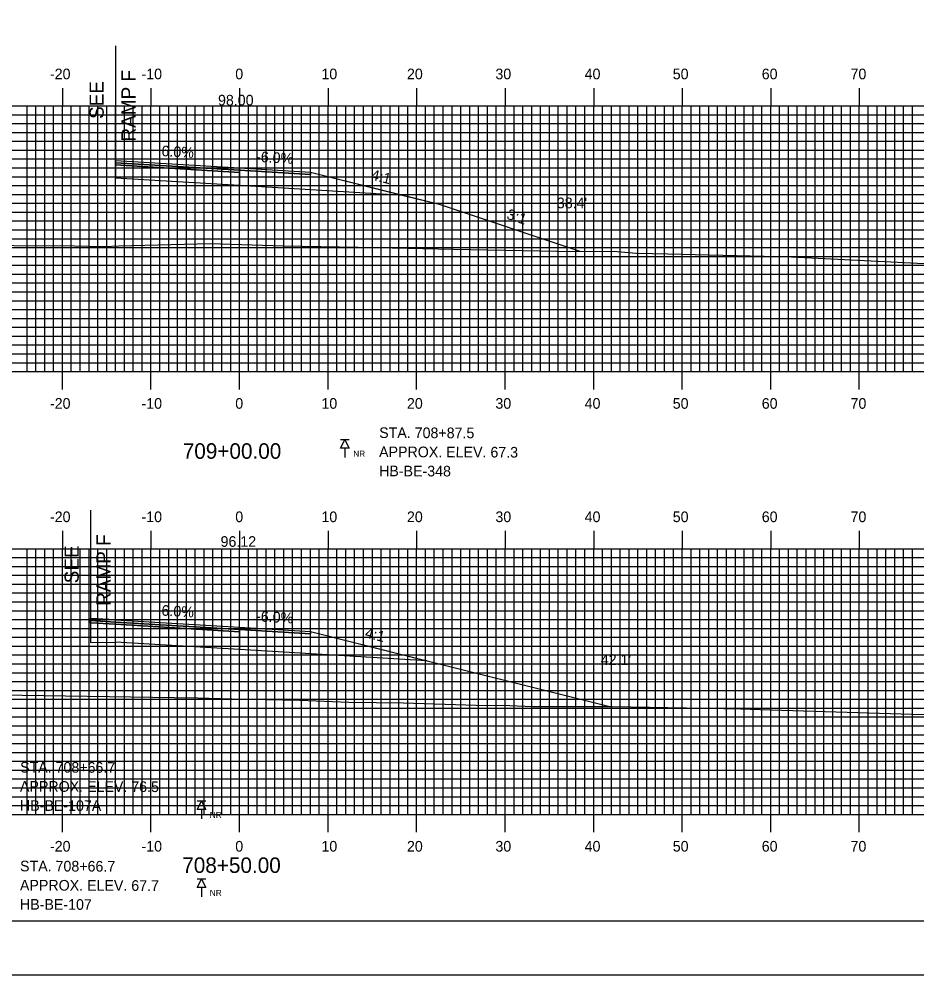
# Model space of a CAD drawing. Extents: x 854510 to 854853, y 364366 to 364586.
# Drawn here: x 854650.8 to 854752.2, y 364365.7 to 364473.6 of the extents above; entities that cross this region are included whole.
import ezdxf

# ---------------------------------------------------------------- set-up
doc = ezdxf.new("R2010")
doc.units = 0
for name, color, linetype in [('ANNOTATION', 7, 'Continuous'), ('BORDER', 7, 'Continuous'), ('BORING - NO REFUSAL', 7, 'Continuous'), ('D_Roadway_Centerline', 7, 'Continuous'), ('D_Roadway_Centerline_Text', 7, 'Continuous'), ('D_Roadway_Edge_Shoulder', 7, 'Continuous'), ('D_Roadway_Edge_TW', 7, 'Continuous'), ('D_Roadway_Pavement', 7, 'Continuous'), ('D_Roadway_SlopeLines', 7, 'Continuous'), ('D_Roadway_SubGrade', 7, 'Continuous'), ('D_Text_Standard', 7, 'Continuous'), ('H_V ANNOTATION', 7, 'Continuous'), ('MAJOR', 7, 'Continuous'), ('MINOR', 7, 'Continuous'), ('PLOT BOUNDARY', 7, 'Continuous'), ('S_Roadway_Centerline', 7, 'Continuous')]:
    doc.layers.add(name, color=color, linetype=linetype)

msp = doc.modelspace()

# ---------------------------------------------------------------- linework, layer by layer
at = {"layer": 'BORDER'}
msp.add_lwpolyline([(854526.14, 364371.79), (854846.14, 364371.79), (854846.14, 364581.79), (854526.14, 364581.79)], close=True, dxfattribs=at)
at = {"layer": 'BORING - NO REFUSAL'}
for p, q in [((854688.12, 364426.09), (854687.16, 364426.09)), ((854687.64, 364425.13), (854687.64, 364424.07)), ((854671.92, 364385.29), (854670.96, 364385.29)), ((854671.44, 364384.33), (854671.44, 364383.27)), ((854671.92, 364376.49), (854670.96, 364376.49)), ((854671.44, 364375.53), (854671.44, 364374.47))]:
    msp.add_line(p, q, dxfattribs=at)
for points in [[(854687.64, 364426.09), (854688.12, 364425.13), (854687.16, 364425.13)], [(854671.44, 364385.29), (854671.92, 364384.33), (854670.96, 364384.33)], [(854671.44, 364376.49), (854671.92, 364375.53), (854670.96, 364375.53)]]:
    msp.add_lwpolyline(points, close=True, dxfattribs=at)
at = {"layer": 'D_Roadway_Centerline'}
msp.add_lwpolyline([(854661.74, 364457.62), (854675.74, 364456.78), (854683.74, 364456.3), (854694.27, 364453.67), (854698.27, 364452.67), (854714.17, 364447.37)], dxfattribs=at)
at = {"layer": 'D_Roadway_Edge_Shoulder'}
for points in [[(854675.74, 364456.78), (854683.74, 364456.3), (854683.74, 364456.05), (854675.74, 364456.53)], [(854661.74, 364405.75), (854658.92, 364405.92), (854658.92, 364405.67), (854661.74, 364405.5)], [(854675.74, 364404.91), (854683.74, 364404.43), (854683.74, 364404.18), (854675.74, 364404.66)]]:
    msp.add_lwpolyline(points, close=True, dxfattribs=at)
at = {"layer": 'D_Roadway_Edge_TW'}
for points in [[(854661.74, 364457.62), (854675.74, 364456.78), (854675.74, 364456.53), (854661.74, 364457.37)], [(854661.74, 364405.75), (854675.74, 364404.91), (854675.74, 364404.66), (854661.74, 364405.5)]]:
    msp.add_lwpolyline(points, close=True, dxfattribs=at)
at = {"layer": 'D_Roadway_Pavement'}
for points in [[(854661.74, 364457.37), (854675.74, 364456.53), (854675.74, 364456.28), (854661.74, 364457.12)], [(854661.74, 364405.5), (854658.92, 364405.67), (854658.92, 364405.42), (854661.74, 364405.25)], [(854661.74, 364405.5), (854675.74, 364404.66), (854675.74, 364404.41), (854661.74, 364405.25)]]:
    msp.add_lwpolyline(points, close=True, dxfattribs=at)
for points in [[(854675.74, 364456.53), (854675.74, 364456.28)], [(854675.74, 364404.66), (854675.74, 364404.41)], [(854675.74, 364404.66), (854675.74, 364404.41)]]:
    msp.add_lwpolyline(points, dxfattribs=at)
at = {"layer": 'D_Roadway_SlopeLines'}
for points in [[(854683.74, 364456.3), (854698.27, 364452.67), (854714.17, 364447.37)], [(854683.74, 364404.43), (854695.74, 364401.43), (854717.57, 364395.97)]]:
    msp.add_lwpolyline(points, dxfattribs=at)
at = {"layer": 'D_Roadway_SubGrade'}
for p, q in [((854661.74, 364470.58), (854661.74, 364455.62)), ((854658.92, 364418.15), (854658.92, 364403.19))]:
    msp.add_line(p, q, dxfattribs=at)
for points in [[(854661.74, 364457.12), (854675.74, 364456.28), (854675.74, 364454.78), (854661.74, 364455.62)], [(854675.74, 364456.28), (854675.74, 364456.53), (854683.74, 364456.05), (854683.74, 364456.3), (854694.27, 364453.67), (854675.74, 364454.78)], [(854661.74, 364405.25), (854658.92, 364405.42), (854658.92, 364405.67), (854658.92, 364405.92), (854658.92, 364403.19), (854661.74, 364403.25)], [(854661.74, 364405.25), (854675.74, 364404.41), (854675.74, 364402.41), (854661.74, 364403.25)], [(854675.74, 364404.41), (854675.74, 364404.66), (854683.74, 364404.18), (854683.74, 364404.43), (854696.9, 364401.14), (854675.74, 364402.41)]]:
    msp.add_lwpolyline(points, close=True, dxfattribs=at)
at = {"layer": 'MAJOR'}
for p, q in [((854655.74, 364465.79), (854655.74, 364463.79)), ((854665.74, 364465.79), (854665.74, 364463.79)), ((854675.74, 364465.79), (854675.74, 364463.79)), ((854685.74, 364465.79), (854685.74, 364463.79)), ((854695.74, 364465.79), (854695.74, 364463.79)), ((854705.74, 364465.79), (854705.74, 364463.79)), ((854715.74, 364465.79), (854715.74, 364463.79)), ((854725.74, 364465.79), (854725.74, 364463.79)), ((854735.74, 364465.79), (854735.74, 364463.79)), ((854745.74, 364465.79), (854745.74, 364463.79)), ((854535.74, 364463.79), (854815.74, 364463.79)), ((854535.74, 364463.79), (854815.74, 364463.79)), ((854655.74, 364433.79), (854655.74, 364463.79)), ((854665.74, 364433.79), (854665.74, 364463.79)), ((854675.74, 364433.79), (854675.74, 364463.79)), ((854685.74, 364433.79), (854685.74, 364463.79)), ((854695.74, 364433.79), (854695.74, 364463.79)), ((854705.74, 364433.79), (854705.74, 364463.79)), ((854715.74, 364433.79), (854715.74, 364463.79)), ((854725.74, 364433.79), (854725.74, 364463.79)), ((854735.74, 364433.79), (854735.74, 364463.79)), ((854745.74, 364433.79), (854745.74, 364463.79)), ((854535.74, 364458.79), (854815.74, 364458.79)), ((854535.74, 364453.79), (854815.74, 364453.79)), ((854535.74, 364448.79), (854815.74, 364448.79)), ((854535.74, 364443.79), (854815.74, 364443.79)), ((854535.74, 364438.79), (854815.74, 364438.79)), ((854535.74, 364433.79), (854815.74, 364433.79)), ((854535.74, 364433.79), (854815.74, 364433.79)), ((854655.74, 364431.78), (854655.74, 364433.79)), ((854665.74, 364431.78), (854665.74, 364433.79)), ((854675.74, 364431.78), (854675.74, 364433.79)), ((854685.74, 364431.78), (854685.74, 364433.79)), ((854695.74, 364431.78), (854695.74, 364433.79)), ((854705.74, 364431.78), (854705.74, 364433.79)), ((854715.74, 364431.78), (854715.74, 364433.79)), ((854725.74, 364431.78), (854725.74, 364433.79)), ((854735.74, 364431.78), (854735.74, 364433.79)), ((854745.74, 364431.78), (854745.74, 364433.79)), ((854655.74, 364415.79), (854655.74, 364413.79)), ((854665.74, 364415.79), (854665.74, 364413.79)), ((854675.74, 364415.79), (854675.74, 364413.79)), ((854685.74, 364415.79), (854685.74, 364413.79)), ((854695.74, 364415.79), (854695.74, 364413.79)), ((854705.74, 364415.79), (854705.74, 364413.79)), ((854715.74, 364415.79), (854715.74, 364413.79)), ((854725.74, 364415.79), (854725.74, 364413.79)), ((854735.74, 364415.79), (854735.74, 364413.79)), ((854745.74, 364415.79), (854745.74, 364413.79)), ((854535.74, 364413.79), (854815.74, 364413.79)), ((854535.74, 364413.79), (854815.74, 364413.79)), ((854655.74, 364383.79), (854655.74, 364413.79)), ((854665.74, 364383.79), (854665.74, 364413.79)), ((854675.74, 364383.79), (854675.74, 364413.79)), ((854685.74, 364383.79), (854685.74, 364413.79)), ((854695.74, 364383.79), (854695.74, 364413.79)), ((854705.74, 364383.79), (854705.74, 364413.79)), ((854715.74, 364383.79), (854715.74, 364413.79)), ((854725.74, 364383.79), (854725.74, 364413.79)), ((854735.74, 364383.79), (854735.74, 364413.79)), ((854745.74, 364383.79), (854745.74, 364413.79)), ((854535.74, 364408.79), (854815.74, 364408.79)), ((854535.74, 364403.79), (854815.74, 364403.79)), ((854535.74, 364398.79), (854815.74, 364398.79)), ((854535.74, 364393.79), (854815.74, 364393.79)), ((854535.74, 364388.79), (854815.74, 364388.79)), ((854535.74, 364383.79), (854815.74, 364383.79)), ((854535.74, 364383.79), (854815.74, 364383.79)), ((854655.74, 364381.78), (854655.74, 364383.79)), ((854665.74, 364381.78), (854665.74, 364383.79)), ((854675.74, 364381.78), (854675.74, 364383.79)), ((854685.74, 364381.78), (854685.74, 364383.79)), ((854695.74, 364381.78), (854695.74, 364383.79)), ((854705.74, 364381.78), (854705.74, 364383.79)), ((854715.74, 364381.78), (854715.74, 364383.79)), ((854725.74, 364381.78), (854725.74, 364383.79)), ((854735.74, 364381.78), (854735.74, 364383.79)), ((854745.74, 364381.78), (854745.74, 364383.79))]:
    msp.add_line(p, q, dxfattribs=at)
at = {"layer": 'MINOR'}
for p, q in [((854651.74, 364433.79), (854651.74, 364463.79)), ((854652.74, 364433.79), (854652.74, 364463.79)), ((854653.74, 364433.79), (854653.74, 364463.79)), ((854654.74, 364433.79), (854654.74, 364463.79)), ((854656.74, 364433.79), (854656.74, 364463.79)), ((854657.74, 364433.79), (854657.74, 364463.79)), ((854658.74, 364433.79), (854658.74, 364463.79)), ((854659.74, 364433.79), (854659.74, 364463.79)), ((854660.74, 364433.79), (854660.74, 364463.79)), ((854661.74, 364433.79), (854661.74, 364463.79)), ((854662.74, 364433.79), (854662.74, 364463.79)), ((854663.74, 364433.79), (854663.74, 364463.79)), ((854664.74, 364433.79), (854664.74, 364463.79)), ((854666.74, 364433.79), (854666.74, 364463.79)), ((854667.74, 364433.79), (854667.74, 364463.79)), ((854668.74, 364433.79), (854668.74, 364463.79)), ((854669.74, 364433.79), (854669.74, 364463.79)), ((854670.74, 364433.79), (854670.74, 364463.79)), ((854671.74, 364433.79), (854671.74, 364463.79)), ((854672.74, 364433.79), (854672.74, 364463.79)), ((854673.74, 364433.79), (854673.74, 364463.79)), ((854674.74, 364433.79), (854674.74, 364463.79)), ((854676.74, 364433.79), (854676.74, 364463.79)), ((854677.74, 364433.79), (854677.74, 364463.79)), ((854678.74, 364433.79), (854678.74, 364463.79)), ((854679.74, 364433.79), (854679.74, 364463.79)), ((854680.74, 364433.79), (854680.74, 364463.79)), ((854681.74, 364433.79), (854681.74, 364463.79)), ((854682.74, 364433.79), (854682.74, 364463.79)), ((854683.74, 364433.79), (854683.74, 364463.79)), ((854684.74, 364433.79), (854684.74, 364463.79)), ((854686.74, 364433.79), (854686.74, 364463.79)), ((854687.74, 364433.79), (854687.74, 364463.79)), ((854688.74, 364433.79), (854688.74, 364463.79)), ((854689.74, 364433.79), (854689.74, 364463.79)), ((854690.74, 364433.79), (854690.74, 364463.79)), ((854691.74, 364433.79), (854691.74, 364463.79)), ((854692.74, 364433.79), (854692.74, 364463.79)), ((854693.74, 364433.79), (854693.74, 364463.79)), ((854694.74, 364433.79), (854694.74, 364463.79)), ((854696.74, 364433.79), (854696.74, 364463.79)), ((854697.74, 364433.79), (854697.74, 364463.79)), ((854698.74, 364433.79), (854698.74, 364463.79)), ((854699.74, 364433.79), (854699.74, 364463.79)), ((854700.74, 364433.79), (854700.74, 364463.79)), ((854701.74, 364433.79), (854701.74, 364463.79)), ((854702.74, 364433.79), (854702.74, 364463.79)), ((854703.74, 364433.79), (854703.74, 364463.79)), ((854704.74, 364433.79), (854704.74, 364463.79)), ((854706.74, 364433.79), (854706.74, 364463.79)), ((854707.74, 364433.79), (854707.74, 364463.79)), ((854708.74, 364433.79), (854708.74, 364463.79)), ((854709.74, 364433.79), (854709.74, 364463.79)), ((854710.74, 364433.79), (854710.74, 364463.79)), ((854711.74, 364433.79), (854711.74, 364463.79)), ((854712.74, 364433.79), (854712.74, 364463.79)), ((854713.74, 364433.79), (854713.74, 364463.79)), ((854714.74, 364433.79), (854714.74, 364463.79)), ((854716.74, 364433.79), (854716.74, 364463.79)), ((854717.74, 364433.79), (854717.74, 364463.79)), ((854718.74, 364433.79), (854718.74, 364463.79)), ((854719.74, 364433.79), (854719.74, 364463.79)), ((854720.74, 364433.79), (854720.74, 364463.79)), ((854721.74, 364433.79), (854721.74, 364463.79)), ((854722.74, 364433.79), (854722.74, 364463.79)), ((854723.74, 364433.79), (854723.74, 364463.79)), ((854724.74, 364433.79), (854724.74, 364463.79)), ((854726.74, 364433.79), (854726.74, 364463.79)), ((854727.74, 364433.79), (854727.74, 364463.79)), ((854728.74, 364433.79), (854728.74, 364463.79)), ((854729.74, 364433.79), (854729.74, 364463.79)), ((854730.74, 364433.79), (854730.74, 364463.79)), ((854731.74, 364433.79), (854731.74, 364463.79)), ((854732.74, 364433.79), (854732.74, 364463.79)), ((854733.74, 364433.79), (854733.74, 364463.79)), ((854734.74, 364433.79), (854734.74, 364463.79)), ((854736.74, 364433.79), (854736.74, 364463.79)), ((854737.74, 364433.79), (854737.74, 364463.79)), ((854738.74, 364433.79), (854738.74, 364463.79)), ((854739.74, 364433.79), (854739.74, 364463.79)), ((854740.74, 364433.79), (854740.74, 364463.79)), ((854741.74, 364433.79), (854741.74, 364463.79)), ((854742.74, 364433.79), (854742.74, 364463.79)), ((854743.74, 364433.79), (854743.74, 364463.79)), ((854744.74, 364433.79), (854744.74, 364463.79)), ((854746.74, 364433.79), (854746.74, 364463.79)), ((854747.74, 364433.79), (854747.74, 364463.79)), ((854748.74, 364433.79), (854748.74, 364463.79)), ((854749.74, 364433.79), (854749.74, 364463.79)), ((854750.74, 364433.79), (854750.74, 364463.79)), ((854751.74, 364433.79), (854751.74, 364463.79)), ((854535.74, 364462.79), (854815.74, 364462.79)), ((854535.74, 364461.79), (854815.74, 364461.79)), ((854535.74, 364460.79), (854815.74, 364460.79)), ((854535.74, 364459.79), (854815.74, 364459.79)), ((854535.74, 364457.79), (854815.74, 364457.79)), ((854535.74, 364456.79), (854815.74, 364456.79)), ((854535.74, 364455.79), (854815.74, 364455.79)), ((854535.74, 364454.79), (854815.74, 364454.79)), ((854535.74, 364452.79), (854815.74, 364452.79)), ((854535.74, 364451.79), (854815.74, 364451.79)), ((854535.74, 364450.79), (854815.74, 364450.79)), ((854535.74, 364449.79), (854815.74, 364449.79)), ((854535.74, 364447.79), (854815.74, 364447.79)), ((854535.74, 364446.79), (854815.74, 364446.79)), ((854535.74, 364445.79), (854815.74, 364445.79)), ((854535.74, 364444.79), (854815.74, 364444.79)), ((854535.74, 364442.79), (854815.74, 364442.79)), ((854535.74, 364441.79), (854815.74, 364441.79)), ((854535.74, 364440.79), (854815.74, 364440.79)), ((854535.74, 364439.79), (854815.74, 364439.79)), ((854535.74, 364437.79), (854815.74, 364437.79)), ((854535.74, 364436.79), (854815.74, 364436.79)), ((854535.74, 364435.79), (854815.74, 364435.79)), ((854535.74, 364434.79), (854815.74, 364434.79)), ((854651.74, 364383.79), (854651.74, 364413.79)), ((854652.74, 364383.79), (854652.74, 364413.79)), ((854653.74, 364383.79), (854653.74, 364413.79)), ((854654.74, 364383.79), (854654.74, 364413.79)), ((854656.74, 364383.79), (854656.74, 364413.79)), ((854657.74, 364383.79), (854657.74, 364413.79)), ((854658.74, 364383.79), (854658.74, 364413.79)), ((854659.74, 364383.79), (854659.74, 364413.79)), ((854660.74, 364383.79), (854660.74, 364413.79)), ((854661.74, 364383.79), (854661.74, 364413.79)), ((854662.74, 364383.79), (854662.74, 364413.79)), ((854663.74, 364383.79), (854663.74, 364413.79)), ((854664.74, 364383.79), (854664.74, 364413.79)), ((854666.74, 364383.79), (854666.74, 364413.79)), ((854667.74, 364383.79), (854667.74, 364413.79)), ((854668.74, 364383.79), (854668.74, 364413.79)), ((854669.74, 364383.79), (854669.74, 364413.79)), ((854670.74, 364383.79), (854670.74, 364413.79)), ((854671.74, 364383.79), (854671.74, 364413.79)), ((854672.74, 364383.79), (854672.74, 364413.79)), ((854673.74, 364383.79), (854673.74, 364413.79)), ((854674.74, 364383.79), (854674.74, 364413.79)), ((854676.74, 364383.79), (854676.74, 364413.79)), ((854677.74, 364383.79), (854677.74, 364413.79)), ((854678.74, 364383.79), (854678.74, 364413.79)), ((854679.74, 364383.79), (854679.74, 364413.79)), ((854680.74, 364383.79), (854680.74, 364413.79)), ((854681.74, 364383.79), (854681.74, 364413.79)), ((854682.74, 364383.79), (854682.74, 364413.79)), ((854683.74, 364383.79), (854683.74, 364413.79)), ((854684.74, 364383.79), (854684.74, 364413.79)), ((854686.74, 364383.79), (854686.74, 364413.79)), ((854687.74, 364383.79), (854687.74, 364413.79)), ((854688.74, 364383.79), (854688.74, 364413.79)), ((854689.74, 364383.79), (854689.74, 364413.79)), ((854690.74, 364383.79), (854690.74, 364413.79)), ((854691.74, 364383.79), (854691.74, 364413.79)), ((854692.74, 364383.79), (854692.74, 364413.79)), ((854693.74, 364383.79), (854693.74, 364413.79)), ((854694.74, 364383.79), (854694.74, 364413.79)), ((854696.74, 364383.79), (854696.74, 364413.79)), ((854697.74, 364383.79), (854697.74, 364413.79)), ((854698.74, 364383.79), (854698.74, 364413.79)), ((854699.74, 364383.79), (854699.74, 364413.79)), ((854700.74, 364383.79), (854700.74, 364413.79)), ((854701.74, 364383.79), (854701.74, 364413.79)), ((854702.74, 364383.79), (854702.74, 364413.79)), ((854703.74, 364383.79), (854703.74, 364413.79)), ((854704.74, 364383.79), (854704.74, 364413.79)), ((854706.74, 364383.79), (854706.74, 364413.79)), ((854707.74, 364383.79), (854707.74, 364413.79)), ((854708.74, 364383.79), (854708.74, 364413.79)), ((854709.74, 364383.79), (854709.74, 364413.79)), ((854710.74, 364383.79), (854710.74, 364413.79)), ((854711.74, 364383.79), (854711.74, 364413.79)), ((854712.74, 364383.79), (854712.74, 364413.79)), ((854713.74, 364383.79), (854713.74, 364413.79)), ((854714.74, 364383.79), (854714.74, 364413.79)), ((854716.74, 364383.79), (854716.74, 364413.79)), ((854717.74, 364383.79), (854717.74, 364413.79)), ((854718.74, 364383.79), (854718.74, 364413.79)), ((854719.74, 364383.79), (854719.74, 364413.79)), ((854720.74, 364383.79), (854720.74, 364413.79)), ((854721.74, 364383.79), (854721.74, 364413.79)), ((854722.74, 364383.79), (854722.74, 364413.79)), ((854723.74, 364383.79), (854723.74, 364413.79)), ((854724.74, 364383.79), (854724.74, 364413.79)), ((854726.74, 364383.79), (854726.74, 364413.79)), ((854727.74, 364383.79), (854727.74, 364413.79)), ((854728.74, 364383.79), (854728.74, 364413.79)), ((854729.74, 364383.79), (854729.74, 364413.79)), ((854730.74, 364383.79), (854730.74, 364413.79)), ((854731.74, 364383.79), (854731.74, 364413.79)), ((854732.74, 364383.79), (854732.74, 364413.79)), ((854733.74, 364383.79), (854733.74, 364413.79)), ((854734.74, 364383.79), (854734.74, 364413.79)), ((854736.74, 364383.79), (854736.74, 364413.79)), ((854737.74, 364383.79), (854737.74, 364413.79)), ((854738.74, 364383.79), (854738.74, 364413.79)), ((854739.74, 364383.79), (854739.74, 364413.79)), ((854740.74, 364383.79), (854740.74, 364413.79)), ((854741.74, 364383.79), (854741.74, 364413.79)), ((854742.74, 364383.79), (854742.74, 364413.79)), ((854743.74, 364383.79), (854743.74, 364413.79)), ((854744.74, 364383.79), (854744.74, 364413.79)), ((854746.74, 364383.79), (854746.74, 364413.79)), ((854747.74, 364383.79), (854747.74, 364413.79)), ((854748.74, 364383.79), (854748.74, 364413.79)), ((854749.74, 364383.79), (854749.74, 364413.79)), ((854750.74, 364383.79), (854750.74, 364413.79)), ((854751.74, 364383.79), (854751.74, 364413.79)), ((854535.74, 364412.79), (854815.74, 364412.79)), ((854535.74, 364411.79), (854815.74, 364411.79)), ((854535.74, 364410.79), (854815.74, 364410.79)), ((854535.74, 364409.79), (854815.74, 364409.79)), ((854535.74, 364407.79), (854815.74, 364407.79)), ((854535.74, 364406.79), (854815.74, 364406.79)), ((854535.74, 364405.79), (854815.74, 364405.79)), ((854535.74, 364404.79), (854815.74, 364404.79)), ((854535.74, 364402.79), (854815.74, 364402.79)), ((854535.74, 364401.79), (854815.74, 364401.79)), ((854535.74, 364400.79), (854815.74, 364400.79)), ((854535.74, 364399.79), (854815.74, 364399.79)), ((854535.74, 364397.79), (854815.74, 364397.79)), ((854535.74, 364396.79), (854815.74, 364396.79)), ((854535.74, 364395.79), (854815.74, 364395.79)), ((854535.74, 364394.79), (854815.74, 364394.79)), ((854535.74, 364392.79), (854815.74, 364392.79)), ((854535.74, 364391.79), (854815.74, 364391.79)), ((854535.74, 364390.79), (854815.74, 364390.79)), ((854535.74, 364389.79), (854815.74, 364389.79)), ((854535.74, 364387.79), (854815.74, 364387.79)), ((854535.74, 364386.79), (854815.74, 364386.79)), ((854535.74, 364385.79), (854815.74, 364385.79)), ((854535.74, 364384.79), (854815.74, 364384.79))]:
    msp.add_line(p, q, dxfattribs=at)
at = {"layer": 'PLOT BOUNDARY'}
msp.add_lwpolyline([(854509.96, 364365.67), (854849.96, 364365.67), (854849.96, 364585.67), (854509.96, 364585.67)], close=True, dxfattribs=at)
at = {"layer": 'S_Roadway_Centerline'}
for points in [[(854643.39, 364448.07), (854657.11, 364448), (854660.48, 364447.92), (854662.11, 364448), (854672.41, 364448.25), (854680.7, 364447.97), (854691.25, 364447.79), (854699.92, 364447.6), (854711.56, 364447.4), (854718.4, 364447.33), (854720.58, 364447.16), (854724.13, 364447.09), (854738.1, 364446.75), (854754.56, 364445.93), (854756.42, 364445.84), (854757.11, 364445.82), (854758.25, 364445.73), (854775.82, 364444.56), (854792.41, 364444.01), (854793.87, 364443.95), (854795.63, 364443.87), (854812.32, 364443.11), (854815.74, 364442.88)], [(854648.75, 364397.28), (854668.36, 364396.97), (854671.03, 364396.95), (854674.88, 364396.84), (854682.56, 364396.7), (854688.07, 364396.46), (854694.27, 364396.4), (854702.47, 364396.11), (854706.24, 364396.08), (854708.87, 364395.99), (854717.83, 364395.97), (854730.44, 364395.76), (854731.27, 364395.74), (854734.56, 364395.64), (854751.7, 364395.12), (854753.72, 364395.06)]]:
    msp.add_lwpolyline(points, dxfattribs=at)

# ---------------------------------------------------------------- texts
at = {"layer": 'ANNOTATION'}
for s, height, rotation, p in [('RAMP F', 1.6, 90, (854664, 364459.76)), ('SEE', 1.6, 90, (854660.4, 364462.31)), ('6.0%', 1.2, 356.5664, (854666.9, 364458.12)), ('-6.0%', 1.2, 356.5664, (854677.58, 364457.48)), ('4:1', 1.2, 345.9638, (854690.51, 364455.47)), ('3:1', 1.2, 341.5652, (854705.82, 364451.06)), ('RAMP F', 1.6, 90, (854661.18, 364407.33)), ('SEE', 1.6, 90, (854657.58, 364409.88)), ('6.0%', 1.2, 356.5664, (854666.9, 364406.24)), ('-6.0%', 1.2, 356.5664, (854677.58, 364405.6)), ('4:1', 1.2, 345.9638, (854689.83, 364403.77))]:
    msp.add_text(s, height=height, rotation=rotation, dxfattribs=at).set_placement(p)
at = {"layer": 'BORING - NO REFUSAL'}
for s, p in [('STA. 708+87.5', (854691.51, 364426.29)), ('APPROX. ELEV. 67.3', (854691.5, 364424.13)), ('HB-BE-348', (854691.5, 364421.97)), ('STA. 708+66.7', (854650.95, 364388.52)), ('APPROX. ELEV. 76.5', (854650.94, 364386.36)), ('HB-BE-107A', (854650.94, 364384.2)), ('STA. 708+66.7', (854650.95, 364377.36)), ('APPROX. ELEV. 67.7', (854650.94, 364375.2)), ('HB-BE-107', (854650.94, 364373.04))]:
    msp.add_text(s, height=1.2, rotation=359.8142, dxfattribs=at).set_placement(p)
for p in [(854688.58, 364424.17), (854672.38, 364383.37), (854672.38, 364374.57)]:
    msp.add_text('NR', height=0.7, dxfattribs=at).set_placement(p)
at = {"layer": 'D_Roadway_Centerline_Text'}
for s, p in [('98.00', (854673.31, 364463.83)), ('96.12', (854673.6, 364414))]:
    msp.add_text(s, height=1.2, dxfattribs=at).set_placement(p)
at = {"layer": 'D_Text_Standard'}
for s, p in [("38.4'", (854711.58, 364452.23)), ("42.1'", (854716.54, 364400.67))]:
    msp.add_text(s, height=1.2, dxfattribs=at).set_placement(p)
at = {"layer": 'H_V ANNOTATION'}
for s, height, p in [('-20', 1.2, (854654.33, 364466.79)), ('-10', 1.2, (854664.67, 364466.79)), ('0', 1.2, (854675.26, 364466.79)), ('10', 1.2, (854684.99, 364466.79)), ('20', 1.2, (854694.65, 364466.79)), ('30', 1.2, (854704.64, 364466.79)), ('40', 1.2, (854714.72, 364466.79)), ('50', 1.2, (854724.67, 364466.79)), ('60', 1.2, (854734.72, 364466.79)), ('70', 1.2, (854744.75, 364466.79)), ('-20', 1.2, (854654.33, 364429.59)), ('-10', 1.2, (854664.67, 364429.59)), ('0', 1.2, (854675.26, 364429.59)), ('10', 1.2, (854684.99, 364429.59)), ('20', 1.2, (854694.65, 364429.59)), ('30', 1.2, (854704.64, 364429.59)), ('40', 1.2, (854714.72, 364429.59)), ('50', 1.2, (854724.67, 364429.59)), ('60', 1.2, (854734.72, 364429.59)), ('70', 1.2, (854744.75, 364429.59)), ('709+00.00', 1.75, (854669.33, 364423.94)), ('-20', 1.2, (854654.33, 364416.79)), ('-10', 1.2, (854664.67, 364416.79)), ('0', 1.2, (854675.26, 364416.79)), ('10', 1.2, (854684.99, 364416.79)), ('20', 1.2, (854694.65, 364416.79)), ('30', 1.2, (854704.64, 364416.79)), ('40', 1.2, (854714.72, 364416.79)), ('50', 1.2, (854724.67, 364416.79)), ('60', 1.2, (854734.72, 364416.79)), ('70', 1.2, (854744.75, 364416.79)), ('-20', 1.2, (854654.33, 364379.59)), ('-10', 1.2, (854664.67, 364379.59)), ('0', 1.2, (854675.26, 364379.59)), ('10', 1.2, (854684.99, 364379.59)), ('20', 1.2, (854694.65, 364379.59)), ('30', 1.2, (854704.64, 364379.59)), ('40', 1.2, (854714.72, 364379.59)), ('50', 1.2, (854724.67, 364379.59)), ('60', 1.2, (854734.72, 364379.59)), ('70', 1.2, (854744.75, 364379.59)), ('708+50.00', 1.75, (854669.27, 364377.18))]:
    msp.add_text(s, height=height, dxfattribs=at).set_placement(p)

doc.saveas('drawing.dxf')
